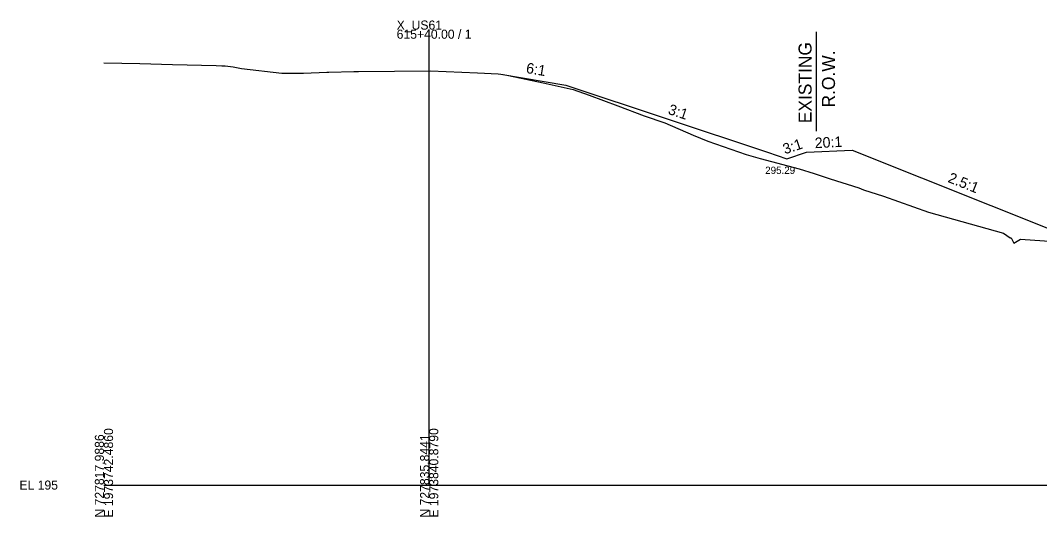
# Model space of a CAD drawing. Extents: x -26 to 1604, y -13 to 9623.
# Drawn here: x -25.7 to 287.7, y 8490.3 to 8642.8 of the extents above; entities that cross this region are included whole.
import ezdxf

# ---------------------------------------------------------------- set-up
doc = ezdxf.new("R2010")
doc.units = 0
for name, color, linetype in [('Draft_XS_Grid', 7, 'Continuous'), ('DTM_X_GROUND', 7, 'Continuous'), ('SLOPE_STAKES_FILL', 7, 'Continuous'), ('XS_CELL', 7, 'Continuous'), ('XS_P_GROUND', 7, 'Continuous'), ('XS_P_TX_DCH', 7, 'Continuous'), ('XS_P_TX_FS_BS', 7, 'Continuous'), ('XS_X_ROW', 7, 'Continuous')]:
    doc.layers.add(name, color=color, linetype=linetype)

msp = doc.modelspace()

# ---------------------------------------------------------------- linework, layer by layer
at = {"layer": 'DTM_X_GROUND'}
msp.add_lwpolyline([(0, 8629.8), (11.03, 8629.54), (21.07, 8629.29), (34.55, 8628.97), (36.2, 8628.91), (37.22, 8628.87), (39.73, 8628.52), (42.24, 8628.1), (54.66, 8626.63), (55.14, 8626.57), (55.18, 8626.57), (61.31, 8626.6), (68.51, 8626.95), (68.61, 8626.95), (68.67, 8626.95), (68.74, 8626.95), (69.19, 8626.96), (76.81, 8627.09), (77.09, 8627.1), (78.26, 8627.14), (89.32, 8627.19), (100.36, 8627.31), (114.85, 8626.69), (121.16, 8626.42), (122.74, 8626.17), (124.4, 8625.91), (135.03, 8623.6), (144.26, 8621.57), (149.2, 8619.81), (157.99, 8616.59), (166.09, 8613.52), (172.43, 8611.32), (181.21, 8607.56), (185.62, 8605.67), (197.45, 8601.6), (201.71, 8600.4), (213.7, 8597.16), (218.35, 8595.79), (223.27, 8594.09), (232.14, 8591.37), (233.52, 8590.71), (239.68, 8588.84), (253.56, 8583.94), (276.57, 8577.4), (278.58, 8575.96), (278.94, 8576.05), (279.79, 8574.41), (281.81, 8575.56), (300.92, 8574.3)], dxfattribs=at)
at = {"layer": 'XS_CELL'}
for p, q in [((100, 8500), (100, 8640)), ((0, 8500), (100, 8500)), ((100, 8500), (600, 8500))]:
    msp.add_line(p, q, dxfattribs=at)
at = {"layer": 'XS_P_GROUND'}
for points in [[(122, 8626.29), (142, 8622.95)], [(142, 8622.95), (204, 8602.29), (210, 8600.29), (216, 8602.29), (230, 8602.99), (294, 8577.39), (300, 8574.99), (306, 8577.39), (320, 8578.09), (342.45, 8569.11)]]:
    msp.add_lwpolyline(points, dxfattribs=at)
at = {"layer": 'XS_X_ROW'}
msp.add_line((219, 8639.36), (219, 8608.81), dxfattribs=at)

# ---------------------------------------------------------------- texts
at = {"layer": 'Draft_XS_Grid'}
msp.add_text('-', height=0.0001, dxfattribs=at).set_placement((0, 8500))
at = {"layer": 'SLOPE_STAKES_FILL'}
for p in [(141.96, 8622.89), (203.96, 8602.23), (215.96, 8602.23), (229.96, 8602.93), (209.96, 8600.23)]:
    msp.add_text('X', height=0.12, dxfattribs=at).set_placement(p)
at = {"layer": 'XS_CELL'}
for s, p in [('X_US61', (90, 8640)), ('615+40.00 / 1', (90, 8637.2)), ('EL 195', (-26, 8498.6))]:
    msp.add_text(s, height=2.8, dxfattribs=at).set_placement(p)
for s, p in [('N 727817.9886', (0, 8490)), ('E 1973742.4860', (2.8, 8490)), ('N 727835.8441', (100, 8490)), ('E 1973840.8790', (102.8, 8490))]:
    msp.add_text(s, height=2.8, rotation=90, dxfattribs=at).set_placement(p)
at = {"layer": 'XS_P_GROUND'}
msp.add_text('X', height=0.12, dxfattribs=at).set_placement((121.96, 8626.23))
at = {"layer": 'XS_P_TX_DCH'}
msp.add_text('295.29', height=2.25, dxfattribs=at).set_placement((203.31, 8595.64))
at = {"layer": 'XS_P_TX_FS_BS'}
for s, rotation, p in [('6:1', 350.5377, (129.62, 8626.7)), ('3:1', 341.5651, (173.21, 8614.15)), ('3:1', 18.4349, (209.35, 8601.64)), ('20:1', 2.8624, (218.63, 8603.55)), ('2.5:1', 338.1986, (259.24, 8593.23))]:
    msp.add_text(s, height=3.24, rotation=rotation, dxfattribs=at).set_placement(p)
at = {"layer": 'XS_X_ROW'}
for s, p in [('EXISTING', (217.57, 8611.22)), ('R.O.W.', (224.77, 8616.07))]:
    msp.add_text(s, height=4, rotation=90, dxfattribs=at).set_placement(p)

doc.saveas('drawing.dxf')
